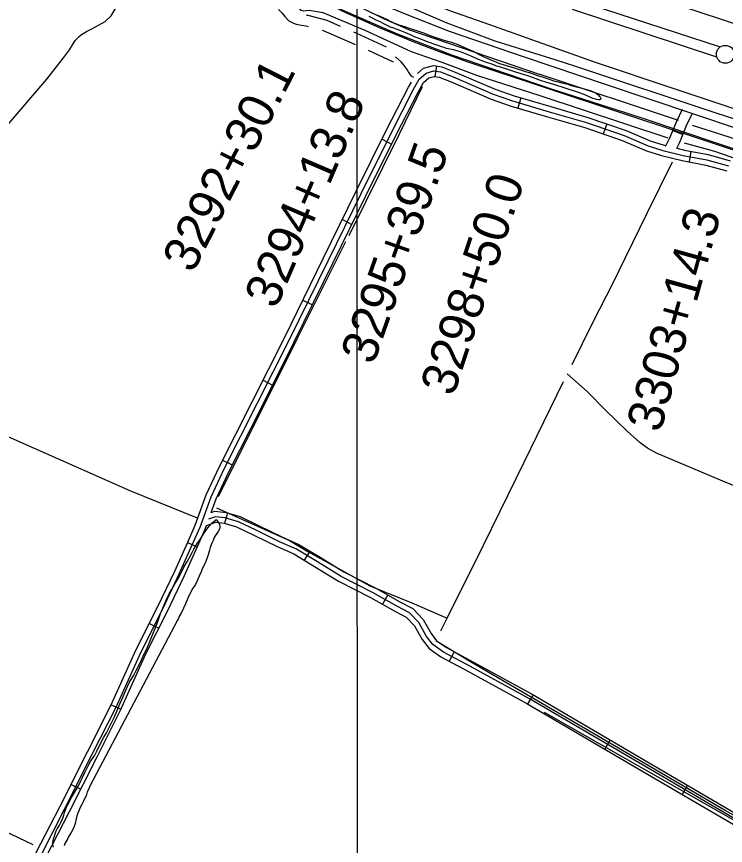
# Model space of a CAD drawing. Extents: x 3281947 to 3319794, y 715894 to 741249.
# Drawn here: x 3295631 to 3297609, y 724593 to 726907 of the extents above; entities that cross this region are included whole.
import ezdxf

# ---------------------------------------------------------------- set-up
doc = ezdxf.new("R2010")
doc.units = 0
for name, color, linetype in [('V-DTCH-CNTR', 7, 'Continuous'), ('V-GRID-MAJR', 7, 'Continuous'), ('V-LEVE-TOET', 7, 'Continuous'), ('V-RAIL-TRAK', 7, 'Continuous'), ('V-ROAD-CNTR', 7, 'Continuous'), ('V-SITE-VEGE', 7, 'Continuous'), ('V-SURV-IDEN', 7, 'Continuous'), ('V-SURV-LINE', 7, 'Continuous'), ('V-TOPO-SHOR', 7, 'Continuous')]:
    doc.layers.add(name, color=color, linetype=linetype)

msp = doc.modelspace()

# ---------------------------------------------------------------- linework, layer by layer
at = {"layer": 'V-DTCH-CNTR'}
msp.add_lwpolyline([(3298264.4, 724283.4), (3298213.5, 724319.8), (3298046, 724418.3), (3297701.2, 724624.6), (3297330.4, 724834.9), (3297103.8, 724964.3)], dxfattribs=at)
at = {"layer": 'V-GRID-MAJR'}
msp.add_spline([(3296583.2, 721277.1), (3296580.6, 727335.7), (3296577.9, 733397.5), (3296575.3, 739459.2), (3296575.3, 739462.3)], degree=3, dxfattribs=at)
at = {"layer": 'V-LEVE-TOET'}
for points in [[(3294520.1, 729099.9), (3294686.2, 728896.2), (3294835.1, 728741.9), (3295011.3, 728529.7), (3295151.6, 728370), (3295217.2, 728306), (3295337.2, 728223.1), (3295601.4, 728029.5), (3295833.1, 727865.9), (3296006.1, 727720.2), (3296224.9, 727569.7), (3296407.4, 727451.2), (3296644.8, 727294.5), (3296700.8, 727256.8), (3296776.5, 727209.8), (3296893.2, 727154.8), (3297031.5, 727100.2), (3297222.7, 727021.5), (3297401.8, 726965.2), (3297667.2, 726876.8)], [(3294339.3, 728953.2), (3294525.8, 728735.3), (3294820.4, 728397.9), (3295067, 728144.5), (3295142.1, 728077.2), (3295249.8, 727995.9), (3295501.2, 727821.5), (3295771, 727618.4), (3295991.4, 727449.3), (3296227.3, 727283.8), (3296424.9, 727134.4), (3296519.9, 727067.6), (3296613.5, 727019.5), (3296766.8, 726953.5), (3296839.1, 726924.5), (3296950.5, 726885.4), (3297245.6, 726780), (3297462.2, 726707.1), (3297806.4, 726592.9), (3298450, 726395.6), (3298661, 726330), (3298816.1, 726284.8), (3298975.8, 726263.9), (3299021.3, 726261.4)]]:
    msp.add_lwpolyline(points, dxfattribs=at)
at = {"layer": 'V-RAIL-TRAK'}
msp.add_lwpolyline([(3297650.7, 726528), (3297483.5, 726583.4), (3297476.6, 726585.6), (3297320, 726637.3), (3297100.8, 726710.5), (3296890.7, 726780.2), (3296813.6, 726808), (3296740.1, 726835.3), (3296643.2, 726875.7), (3296543.9, 726920.2), (3296445.5, 726969.6), (3296361.3, 727015.9), (3296300.2, 727051.7), (3296229.7, 727095.4), (3296145.7, 727150.7), (3296056.4, 727214.8), (3295976.1, 727275.6), (3295893.8, 727341), (3295818.4, 727401.5), (3295714.8, 727483.6), (3295573.1, 727597.3), (3295474.8, 727675.6), (3295388.1, 727745.3), (3295268.7, 727840.9)], dxfattribs=at)
at = {"layer": 'V-ROAD-CNTR'}
for p, q in [((3296611.4, 726813), (3296681.4, 726781.1)), ((3296802.6, 726769.5), (3296797.9, 726739.8)), ((3297037.7, 726680.5), (3297029.2, 726651.7)), ((3297277.5, 726607.7), (3297267.8, 726579.3)), ((3297462.3, 726589.4), (3297490, 726577.9)), ((3296650.4, 726564.5), (3296677.3, 726551.2)), ((3297512.5, 726531.1), (3297507, 726501.6)), ((3296539.7, 726340.3), (3296566.6, 726327)), ((3296429.6, 726115.8), (3296456.5, 726102.6)), ((3296318.3, 725892.1), (3296345.1, 725878.6)), ((3296205.7, 725669), (3296232.5, 725655.4)), ((3296219.3, 725521.3), (3296211, 725492.5)), ((3296107.4, 725438.6), (3296134.8, 725426.4)), ((3296449.2, 725414.9), (3296433.6, 725389.3)), ((3296666.4, 725292.5), (3296651.6, 725266.4)), ((3296001.2, 725213.2), (3296027.9, 725199.6)), ((3296851.7, 725134.1), (3296837.6, 725107.6)), ((3297071.7, 725014.1), (3297056.5, 724988.2)), ((3295894.9, 724986.2), (3295922.3, 724973.9)), ((3297287.4, 724887.7), (3297272.2, 724861.8)), ((3295782.7, 724763.5), (3295809.5, 724750)), ((3297503.1, 724761.4), (3297488, 724735.5))]:
    msp.add_line(p, q, dxfattribs=at)
for points in [[(3294412.2, 728781.8), (3294690.1, 728464.3), (3294780, 728360.7), (3294834.2, 728303.8), (3294878.7, 728257.7), (3294924.3, 728208.5), (3294973.4, 728163.1), (3295032.6, 728108.6), (3295124.6, 728032.6), (3295333, 727871.1), (3295637.9, 727638.8), (3295917.9, 727429.4), (3296214.5, 727208.2), (3296344.2, 727112.5), (3296384, 727086.6), (3296426.1, 727061.9), (3296481.5, 727027), (3296535.1, 726997.1), (3296611.7, 726958.6), (3296710.2, 726916.7), (3296837.3, 726866.6), (3297047.5, 726794.6), (3297275.9, 726718), (3297644.1, 726594.2)], [(3294297.2, 728619.1), (3294633, 728351.3), (3295063.6, 728007.8), (3295320.2, 727801), (3295667.6, 727522.5), (3295906.8, 727334.3), (3295994.2, 727263.1), (3296065.3, 727209.4), (3296119.9, 727170), (3296185.2, 727126), (3296278.2, 727066.6), (3296387, 727005.4), (3296471.8, 726957.1), (3296571.2, 726911.9), (3296692.4, 726859.1), (3296844.1, 726800.6), (3297117.2, 726707.5), (3297377.8, 726624), (3297593.5, 726551.1), (3297846, 726465.9)], [(3296361.2, 726927), (3296372.1, 726916.5), (3296379, 726907.1), (3296390.3, 726895.4), (3296403.6, 726889.2), (3296410.9, 726886.2), (3296420.5, 726883.9), (3296437.7, 726881.4), (3296444.5, 726879.5)], [(3296439.3, 726911.4), (3296443.8, 726910.8), (3296496.2, 726896.7), (3296534, 726880.3)], [(3296483.2, 726869.2), (3296486.3, 726868.3), (3296565.1, 726834.1), (3296575, 726829.6)], [(3296570.7, 726864.4), (3296577.3, 726861.5), (3296661.8, 726823)], [(3296739.2, 726736.7), (3296732.9, 726741), (3296724.4, 726752.5), (3296720.5, 726759.1), (3296715.4, 726766.9), (3296709.1, 726774.6), (3296703.7, 726780.6), (3296687.6, 726794.8)], [(3295698.8, 724566.5), (3295764.6, 724694.4), (3295842, 724847.8), (3295907.3, 724977.1), (3295977.9, 725134.1), (3296038.7, 725253.9), (3296085.7, 725353.1), (3296121.8, 725434.2), (3296143.3, 725481.5), (3296173.4, 725566.7), (3296210.2, 725644.7), (3296302.2, 725826.6), (3296392.3, 726005.7), (3296500, 726225.5), (3296592.1, 726412.9), (3296675.8, 726581.9), (3296737.7, 726702.8), (3296754.2, 726732.9), (3296773.4, 726749.3), (3296795.2, 726755.4), (3296813.6, 726752.5), (3296848.9, 726738.5), (3296960.4, 726690.2), (3297014.9, 726671.6), (3297116.8, 726641.4), (3297220.6, 726611.4), (3297326.3, 726575.1), (3297393.3, 726546.3), (3297433.9, 726533.5), (3297491.1, 726519.8), (3297557.2, 726507.4), (3297616.9, 726490.5)], [(3296749.3, 726748.4), (3296766.2, 726762.9), (3296794.3, 726770.8), (3296817.6, 726767.1), (3296854.6, 726752.3), (3296965.8, 726704.2), (3297019.5, 726685.9), (3297121, 726655.8), (3297225.1, 726625.7), (3297331.7, 726589.1), (3297398.5, 726560.4), (3297438, 726547.9), (3297442.5, 726546.8)], [(3296173.7, 725522.6), (3296187.3, 725561), (3296223.7, 725638.2), (3296315.5, 725819.8), (3296405.7, 725999.1), (3296513.5, 726218.9), (3296605.6, 726406.3), (3296689.2, 726575.2), (3296751, 726695.8), (3296766.1, 726723.3), (3296780.7, 726735.8), (3296796.1, 726740.1), (3296809.6, 726738), (3296843.1, 726724.6), (3296955, 726676.2), (3297010.4, 726657.3), (3297112.6, 726627), (3297216, 726597.1), (3297320.9, 726561.1), (3297388, 726532.3), (3297429.9, 726519), (3297488, 726505.1), (3297553.7, 726492.8), (3297612.1, 726476.3)], [(3295644.7, 724497.6), (3295685.6, 724573.5), (3295751.2, 724701.2), (3295828.6, 724854.5), (3295893.7, 724983.6), (3295964.3, 725140.6), (3296025.2, 725260.5), (3296072.1, 725359.3), (3296108.1, 725440.3), (3296129.4, 725487.2), (3296159.5, 725572.4), (3296196.8, 725651.3), (3296288.8, 725833.3), (3296378.9, 726012.4), (3296486.6, 726232.1), (3296578.7, 726419.6), (3296662.4, 726588.7), (3296724.5, 726709.8), (3296732.4, 726724.4)], [(3297442.5, 726546.8), (3297453.7, 726568.8), (3297473, 726615.1), (3297489, 726648.3)], [(3297472.6, 726539.7), (3297481, 726556.2), (3297500.4, 726602.8), (3297516, 726635.3)], [(3297472.6, 726539.7), (3297494.2, 726534.5), (3297560.6, 726522.1), (3297621.7, 726504.8)], [(3296173.7, 725522.6), (3296183.6, 725526.1), (3296215.9, 725522.3), (3296254.8, 725511.1), (3296305.5, 725486.7), (3296370.6, 725454.8), (3296418.5, 725433.6), (3296477.7, 725397.6), (3296543.9, 725357.3), (3296633, 725311.4), (3296700.4, 725273.2), (3296736.1, 725254.4), (3296764.9, 725224.3), (3296787.2, 725184.5), (3296802.8, 725164.8), (3296829.9, 725145.7), (3296894, 725111.6), (3297069.2, 725015.5), (3297395.5, 724824.3), (3297750.3, 724616.8), (3298093.5, 724416.6), (3298272.7, 724307.4)], [(3298264.9, 724294.6), (3298085.8, 724403.7), (3297742.8, 724603.9), (3297388, 724811.4), (3297061.8, 725002.5), (3296886.8, 725098.4), (3296822, 725133), (3296792.4, 725153.8), (3296774.7, 725176.1), (3296752.8, 725215.3), (3296727, 725242.3), (3296693.2, 725260), (3296625.9, 725298.2), (3296536.6, 725344.2), (3296469.9, 725384.8), (3296411.6, 725420.2), (3296364.2, 725441.2), (3296299, 725473.2), (3296249.5, 725497.1), (3296213, 725507.5), (3296185.3, 725510.8), (3296166.6, 725504.2)], [(3295671.2, 724483.4), (3295712.1, 724559.5), (3295778, 724687.6), (3295855.4, 724841), (3295920.8, 724970.7), (3295991.4, 725127.7), (3296052.1, 725247.2), (3296099.3, 725346.8), (3296135.5, 725428), (3296157.2, 725475.9), (3296160.9, 725486.2)], [(3296160.9, 725486.2), (3296187, 725495.5), (3296210, 725492.8), (3296244.1, 725483), (3296292.4, 725459.7), (3296357.9, 725427.6), (3296404.6, 725406.9), (3296462.1, 725372), (3296529.2, 725331.1), (3296618.7, 725285), (3296686, 725246.9), (3296717.8, 725230.1), (3296740.6, 725206.3), (3296762.2, 725167.7), (3296782, 725142.8), (3296814.1, 725120.2), (3296879.7, 725085.2), (3297054.4, 724989.4), (3297380.4, 724798.4), (3297735.2, 724590.9), (3298078.1, 724390.8), (3298257.1, 724281.8)]]:
    msp.add_lwpolyline(points, dxfattribs=at)
at = {"layer": 'V-SITE-VEGE'}
for points in [[(3296635.5, 726911.8), (3296654.2, 726903.4), (3296663.3, 726900.2), (3296665.1, 726898.9), (3296667.5, 726897.7), (3296672.4, 726894.7), (3296675.6, 726893.1), (3296680.9, 726890.4), (3296691, 726886.6), (3296697, 726884.5), (3296715.9, 726878.4), (3296723.8, 726875.5), (3296763.3, 726862.6), (3296789.7, 726852.4), (3296823.2, 726841.6), (3296847, 726835), (3296853.4, 726832.4), (3296857.1, 726831.1), (3296870.4, 726825.8), (3296897.4, 726813.7), (3296904.5, 726810.2), (3296921.2, 726801.3), (3296934.1, 726795.2), (3296963.2, 726782.6), (3296978.3, 726776.5), (3296988.4, 726773), (3296999.7, 726769.5), (3297016, 726765.2), (3297048.3, 726755.2), (3297059.7, 726751.3), (3297061.8, 726750.7), (3297084.3, 726742.9), (3297094, 726740), (3297100.1, 726738), (3297108.3, 726735.5), (3297114.2, 726733.3), (3297129.5, 726728.2), (3297141.8, 726724.7), (3297152, 726722.6), (3297169.2, 726718.1), (3297175.4, 726715.8), (3297185.5, 726712.7), (3297193.1, 726710.9), (3297200.8, 726709.2), (3297228.4, 726701.8), (3297234, 726699.8), (3297238.7, 726697.7), (3297245.8, 726694.1), (3297252.8, 726689.4), (3297258.5, 726683.4), (3297260.1, 726681), (3297261.2, 726678.4), (3297259.8, 726676), (3297257.4, 726674.9), (3297254.4, 726675.1), (3297248.5, 726676.1), (3297236.8, 726679.6), (3297234.8, 726680.6), (3297214.2, 726689.2), (3297198.5, 726694.9), (3297126.6, 726718.6), (3297110.6, 726723), (3297092.7, 726729.1), (3297070.7, 726737.1), (3297057, 726741.4), (3297044.9, 726745.5), (3297024.2, 726752), (3297006.8, 726757.3), (3296975.4, 726768), (3296969.8, 726769.2), (3296967.9, 726769.8), (3296964.5, 726771.3), (3296958.7, 726773.3), (3296954.8, 726774.9), (3296947.2, 726777.4), (3296936.7, 726781.3), (3296929.4, 726783.7), (3296924.2, 726785.7), (3296901.2, 726795.7), (3296892.5, 726799.2), (3296883.4, 726803), (3296869.3, 726808.5), (3296856.6, 726812.4), (3296849.8, 726814.1)], [(3296849.8, 726814.1), (3296830, 726818.4), (3296823.8, 726820.7), (3296820, 726822.1), (3296809.3, 726825.6), (3296806.7, 726826.2), (3296797, 726829.3), (3296788.5, 726832.6), (3296782.3, 726834.6), (3296755.8, 726844.6), (3296741.1, 726850.7), (3296729.4, 726855.8), (3296716.9, 726861.5), (3296703, 726867.4), (3296683.8, 726875.1), (3296673.7, 726878), (3296671.7, 726878.8), (3296668.3, 726880.6), (3296657.6, 726885.7), (3296653.6, 726887.9), (3296646.9, 726891.3), (3296638.8, 726895.2), (3296634.2, 726897.6), (3296623.7, 726902.7), (3296614.8, 726907.6)], [(3296048, 725278.1), (3296056.6, 725295.2), (3296063.4, 725306.4), (3296074.2, 725326.4), (3296082.7, 725339.7), (3296091.8, 725357.7), (3296097.4, 725370.2), (3296107.7, 725386.4), (3296112, 725395.2), (3296120.6, 725411.4), (3296125.3, 725420.6), (3296134.7, 725436), (3296142.8, 725447.2), (3296148.8, 725456.3), (3296154.8, 725466.7), (3296158.7, 725472.6), (3296162.1, 725477.1), (3296166.8, 725483.8), (3296176.2, 725494.2), (3296185.5, 725501.6), (3296187.2, 725502.8), (3296190.5, 725499.8), (3296196.7, 725489.7), (3296197.8, 725482.6), (3296197.3, 725476.3)], [(3296197.3, 725476.3), (3296193.5, 725469.6), (3296189.2, 725464.2), (3296184.5, 725458), (3296181.9, 725452.6), (3296178.9, 725444.2), (3296175.9, 725437.1), (3296171.1, 725425.4), (3296168.9, 725417.9), (3296165.4, 725404.5), (3296162.3, 725395.8), (3296156.7, 725381.6), (3296148.9, 725365.3), (3296145.9, 725357), (3296140.3, 725345.3), (3296129.5, 725321.5), (3296122.6, 725311.1), (3296112.8, 725294), (3296108.4, 725283.2), (3296101.9, 725267.8), (3296090.7, 725243.2), (3296085.6, 725234.4), (3296081.3, 725224.8), (3296079.5, 725221.9), (3295835.7, 724760.7), (3295834, 724756.1), (3295831, 724749.4), (3295828, 724743.2), (3295824.9, 724731.9), (3295821, 724724.8), (3295816.7, 724715.2), (3295813.3, 724709.4), (3295809, 724700.6), (3295801.2, 724683.5), (3295799, 724675.6), (3295797.2, 724667.7), (3295793.7, 724654.3), (3295791.5, 724646.3), (3295786.7, 724635.5), (3295783.3, 724629.2), (3295776.9, 724619.3), (3295773.8, 724613), (3295765.7, 724598.4), (3295763.1, 724592.6)], [(3295733.3, 724588.8), (3295732.1, 724595.5), (3295732.2, 724600.1), (3295733.1, 724606.4), (3295733.6, 724611.4), (3295736.2, 724618.9), (3295737.9, 724625.6), (3295741, 724634), (3295744, 724639.8), (3295750, 724650.2), (3295753.9, 724657.3), (3295759.5, 724669), (3295762.5, 724677.3), (3295764.7, 724685.3), (3295771.2, 724702.8), (3295774.2, 724708.6), (3295780.7, 724722.4), (3295786.7, 724731.6), (3295798.3, 724750.7), (3295803, 724759.4), (3295809.5, 724773.6), (3295814.6, 724782.8), (3295821.5, 724797), (3295827.1, 724807.8), (3295831.9, 724819.1), (3295838.3, 724829.5), (3295849, 724845.3), (3295855, 724856.5), (3295864.9, 724878.2), (3295874, 724895.3), (3295881.3, 724907.8), (3295890.3, 724924), (3295895.5, 724935.3), (3295903.6, 724951.9), (3295914.9, 724979.5), (3295919.7, 724990.7), (3295924.9, 725002.8), (3295930.9, 725015.8), (3295939.1, 725035), (3295946, 725048.7), (3295957.6, 725068.3), (3295964, 725081.6), (3295975.2, 725103.3), (3295983, 725120), (3295996.4, 725147.1), (3296004.6, 725167.1), (3296023.7, 725215.5), (3296032, 725241), (3296038.4, 725255.2), (3296043.2, 725266.8), (3296048, 725278.1)]]:
    msp.add_lwpolyline(points, dxfattribs=at)
at = {"layer": 'V-SURV-LINE'}
for points in [[(3297191.1, 726955.2), (3297594.1, 726822.4)], [(3297584.7, 726793.9), (3297181.7, 726926.7)]]:
    msp.add_lwpolyline(points, dxfattribs=at)
msp.add_circle((3297608.4, 726801.9), 25, dxfattribs=at)
at = {"layer": 'V-TOPO-SHOR'}
for p, q in [((3297477.9, 726617.2), (3297092.1, 726745.6)), ((3297693.4, 726546.9), (3297517, 726602.8)), ((3296814.2, 725191.9), (3296832.2, 725227.9))]:
    msp.add_line(p, q, dxfattribs=at)
for points in [[(3294597.3, 728608.2), (3294667.2, 728530.2), (3294849.6, 728327.1), (3294926.1, 728251.9), (3295046.5, 728134.7), (3295129.6, 728064), (3295212.8, 727995.5), (3295459.8, 727808), (3295612.5, 727696.7), (3295999.8, 727411.1), (3296254.6, 727220.4), (3296396, 727119), (3296499.2, 727054), (3296576.6, 727007.8), (3296686.4, 726951.9), (3296830.8, 726889.6), (3296965.1, 726839.4), (3297132.9, 726787.3), (3297189.9, 726768.8), (3297581.5, 726638.4), (3297723.5, 726592.7)], [(3295302.8, 727840.4), (3295580.7, 727634.1), (3295667.6, 727572.7), (3295890.3, 727407.1), (3295981.6, 727335.1), (3296125.8, 727225.7), (3296239.4, 727135), (3296293.4, 727100.7), (3296480.9, 726988.5), (3296654.5, 726901.5), (3296724.3, 726871.5), (3297092.1, 726745.6)], [(3297448.8, 726567.4), (3297091.6, 726685.5), (3296915.1, 726743), (3296817.8, 726779.1), (3296732.2, 726808.9), (3296603.1, 726867.9), (3296485.7, 726917.4), (3296446.7, 726924.5), (3296430.9, 726922.2), (3296424.6, 726924.3), (3296415, 726937.9), (3296353.5, 726979.5), (3296242.2, 727055.5), (3296163.7, 727108.5), (3296013.2, 727215.3), (3295907.1, 727299.7), (3295831.7, 727359.1), (3295585.5, 727561.4), (3295270.4, 727803.2)], [(3295839, 726872.1), (3295859.3, 726882.8), (3295877.6, 726893.6), (3295894.9, 726909.1), (3295923.8, 726959), (3295971.3, 727054.8), (3296018.4, 727147.5)], [(3295604.7, 726602.8), (3295714.9, 726732.1), (3295761.8, 726792), (3295778.5, 726814.3), (3295788.2, 726831.1), (3295794.2, 726840.2), (3295805.5, 726852), (3295811.9, 726857.4), (3295825.8, 726865.7), (3295839, 726872.1)], [(3296558.7, 726296.3), (3296700.1, 726581.5), (3296762.9, 726711.9)], [(3298752.9, 726137.1), (3298651.5, 726159.4), (3298588.1, 726184.2), (3298462.3, 726232.6), (3298250.9, 726302.5), (3298042.7, 726374.4), (3297688.6, 726492.6), (3297578.7, 726530.6), (3297494.2, 726554.1)], [(3297460.2, 726500.5), (3297389.5, 726357), (3297328.6, 726233.3), (3297295.7, 726165.2), (3297237.9, 726051.8), (3297179.9, 725934.5)], [(3296194.2, 725567.5), (3296416.5, 726012.9), (3296549.4, 726279.4)], [(3296135.4, 725506.5), (3295949.9, 725582.5), (3295680.6, 725701.8), (3295473.8, 725792.9), (3295280.5, 725877.6), (3295217.8, 725906.2)], [(3297416.7, 725688), (3297390.8, 725702.7), (3297370.3, 725717.5), (3297334.7, 725749.9), (3297274.1, 725808.3), (3297222.7, 725860.4), (3297166.8, 725909.9)], [(3296832.2, 725227.9), (3296933.3, 725431.2), (3297047.2, 725663.5), (3297157.1, 725888.1)], [(3298408.1, 725276.6), (3298102.9, 725404.1), (3297601.1, 725610.1), (3297416.7, 725688)], [(3296188.3, 725535.5), (3296392.2, 725445), (3296443.8, 725413.5), (3296616.4, 725317.9), (3296733.7, 725270.2), (3296832.2, 725227.9)], [(3297607.8, 724691.2), (3297227.9, 724913), (3296901.9, 725102.6), (3296800.5, 725164.5)], [(3298259.6, 724311.7), (3298198.4, 724347.8), (3298122.9, 724393.9), (3298051.5, 724435.4), (3297961.5, 724486.9), (3297852.6, 724552.3), (3297719, 724628.3), (3297607.8, 724691.2)], [(3295677.1, 724594.5), (3295594.8, 724633.8), (3295495.2, 724673), (3295465.9, 724687.2)]]:
    msp.add_lwpolyline(points, dxfattribs=at)

# ---------------------------------------------------------------- texts
at = {"layer": 'V-SURV-IDEN'}
for s, rotation, p in [('3292+30.1', 63.0033, (3296122.3, 726187.7)), ('3294+13.8', 66.7697, (3296354.8, 726088)), ('3295+39.5', 70.6194, (3296626.6, 725932.3)), ('3298+50.0', 71.7325, (3296849.8, 725844.2)), ('3303+14.3', 74.5077, (3297427.1, 725743))]:
    msp.add_text(s, height=100, rotation=rotation, dxfattribs=at).set_placement(p)

doc.saveas('drawing.dxf')
